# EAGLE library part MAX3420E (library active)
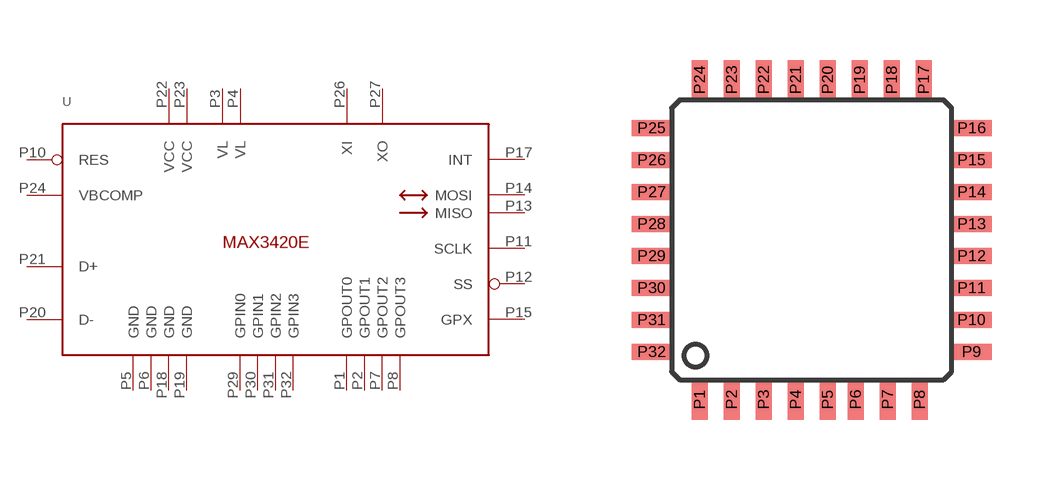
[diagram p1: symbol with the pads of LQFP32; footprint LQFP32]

Designator prefix U

## MAX3420ELQFP32  [LQFP32]
P1  GPOUT0  out
P2  GPOUT1  out
P3  VL  pwr
P4  VL  pwr
P5  GND  pwr
P6  GND  pwr
P7  GPOUT2  out
P8  GPOUT3  out
P10  RES  in
P11  SCLK  in
P12  SS  in
P13  MISO  out
P14  MOSI
P15  GPX  out
P17  INT  out
P18  GND  pwr
P19  GND  pwr
P20  D-
P21  D+
P22  VCC  pwr
P23  VCC  pwr
P24  VBCOMP  in
P26  XI  pas
P27  XO  pas
P29  GPIN0  in
P30  GPIN1  in
P31  GPIN2  in
P32  GPIN3  in

## Footprint LQFP32 (pad centres in mm)
smd 0.4 x 1: P1 -2.8,-4; P2 -2,-4; P3 -1.2,-4; P4 -0.4,-4; P5 0.4,-4; P6 1.1,-4; P7 1.9,-4; P8 2.7,-4; P17 2.8,4; P18 2,4; P19 1.2,4; P20 0.4,4; P21 -0.4,4; P22 -1.2,4; P23 -2,4; P24 -2.8,4
smd 1 x 0.4: P9 4,-2.8; P10 4,-2; P11 4,-1.2; P12 4,-0.4; P13 4,0.4; P14 4,1.2; P15 4,2; P16 4,2.8; P25 -4,2.8; P26 -4,2; P27 -4,1.2; P28 -4,0.4; P29 -4,-0.4; P30 -4,-1.2; P31 -4,-2; P32 -4,-2.8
